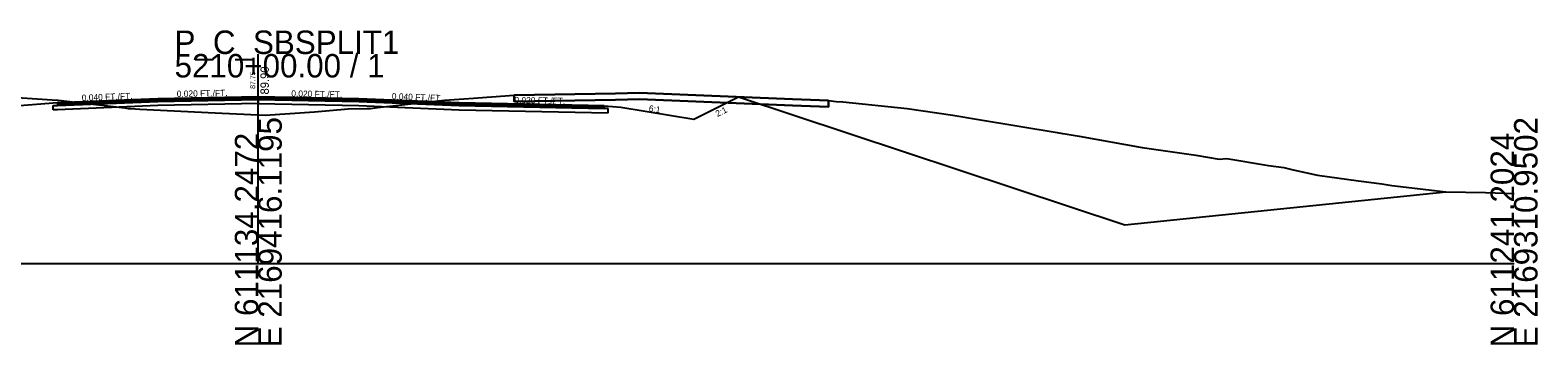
# Model space of a CAD drawing. Extents: x -26 to 1303, y -3010 to 12033.
# Drawn here: x 1122.8 to 1302.8, y 6990.3 to 7027.8 of the extents above; entities that cross this region are included whole.
import ezdxf

# ---------------------------------------------------------------- set-up
doc = ezdxf.new("R2010")
doc.units = 0
for name, color, linetype in [('RD_GPK_XS_Cell', 7, 'Continuous'), ('RD_Sketch10', 7, 'Continuous'), ('RD_XS_Base', 7, 'Continuous'), ('RD_XS_ExGround', 7, 'Continuous'), ('RD_XS_ExPaveRet', 7, 'Continuous'), ('RD_XS_Greenside', 7, 'Continuous'), ('RD_XS_Pave', 7, 'Continuous'), ('RD_XS_PaveOvlay_CP', 7, 'Continuous'), ('RD_XS_TieSlope', 7, 'Continuous'), ('RD_XS_TX_Elev_EX', 7, 'Continuous'), ('RD_XS_TX_Elev_PR', 7, 'Continuous'), ('RD_XS_TX_Slope', 7, 'Continuous')]:
    doc.layers.add(name, color=color, linetype=linetype)

msp = doc.modelspace()

# ---------------------------------------------------------------- linework, layer by layer
at = {"layer": 'RD_GPK_XS_Cell'}
for p, q in [((1150, 7000), (1150, 7025)), ((1000, 7000), (1150, 7000)), ((1150, 7000), (1300, 7000))]:
    msp.add_line(p, q, dxfattribs=at)
at = {"layer": 'RD_Sketch10'}
msp.add_lwpolyline([(1207.36, 7019.88), (1253.51, 7004.61), (1291.86, 7008.57)], dxfattribs=at)
at = {"layer": 'RD_XS_Base'}
for p, q in [((1125.5, 7018.84), (1126, 7018.86)), ((1125.5, 7018.34), (1125.5, 7018.84)), ((1125.5, 7018.84), (1125.5, 7018.84)), ((1126, 7018.36), (1125.5, 7018.34)), ((1125.5, 7018.34), (1125.5, 7018.34)), ((1125.5, 7018.34), (1125.5, 7018.34)), ((1126, 7018.86), (1138, 7019.34)), ((1126, 7018.86), (1126, 7018.86)), ((1138, 7018.84), (1126, 7018.36)), ((1126, 7018.36), (1126, 7018.36)), ((1136, 7019.26), (1136, 7019.26)), ((1136, 7018.76), (1136, 7018.76)), ((1138, 7019.34), (1150, 7019.58)), ((1150, 7019.08), (1138, 7018.84)), ((1150, 7019.58), (1150, 7019.74)), ((1150, 7019.74), (1150, 7019.08)), ((1150, 7019.58), (1150, 7019.08)), ((1150, 7019.58), (1150, 7019.58)), ((1162, 7019.34), (1150, 7019.58)), ((1150, 7019.58), (1150, 7019.58)), ((1150, 7019.08), (1150, 7019.08)), ((1150, 7019.08), (1150, 7019.08)), ((1150, 7019.08), (1162, 7018.84)), ((1174, 7018.86), (1162, 7019.34)), ((1162, 7019.34), (1162, 7019.34)), ((1162, 7018.84), (1162, 7018.84)), ((1162, 7018.84), (1174, 7018.36)), ((1191.3, 7018.51), (1174, 7018.86)), ((1174, 7018.86), (1174, 7018.86)), ((1174, 7018.36), (1174, 7018.36)), ((1174, 7018.36), (1191.8, 7018)), ((1191.8, 7018.5), (1191.3, 7018.51)), ((1191.3, 7018.51), (1191.3, 7018.51)), ((1191.8, 7018), (1191.8, 7018.5)), ((1191.8, 7018.5), (1191.8, 7018.5)), ((1191.8, 7018), (1191.8, 7018)), ((1191.8, 7018), (1191.8, 7018))]:
    msp.add_line(p, q, dxfattribs=at)
at = {"layer": 'RD_XS_ExGround'}
msp.add_lwpolyline([(1116.42, 7020.14), (1125.36, 7019.55), (1126.03, 7019.51), (1126.08, 7019.51), (1134.06, 7018.56), (1134.47, 7018.5), (1134.56, 7018.5), (1134.72, 7018.49), (1135.86, 7018.43), (1144.86, 7017.97), (1150.84, 7017.71), (1156.71, 7018.12), (1160.72, 7018.44), (1162.99, 7018.49), (1163.39, 7018.51), (1164.24, 7018.6), (1172.26, 7019.5), (1175.15, 7019.69), (1180.58, 7020.08), (1192.67, 7020.3), (1195.54, 7020.36), (1213.82, 7019.62), (1218.12, 7019.45), (1219.03, 7019.35), (1219.82, 7019.28), (1227.5, 7018.5), (1232.97, 7017.69), (1236.04, 7017.2), (1245.43, 7015.63), (1246.05, 7015.5), (1246.36, 7015.49), (1248.04, 7015.19), (1255.58, 7013.86), (1261.98, 7012.94), (1264.77, 7012.47), (1265.69, 7012.55), (1270.65, 7011.69), (1272.51, 7011.45), (1273.63, 7011.2), (1276.52, 7010.54), (1281.42, 7009.87), (1284.21, 7009.5), (1285.38, 7009.31), (1291.86, 7008.57), (1296.6, 7008.47), (1300, 7008.36)], dxfattribs=at)
at = {"layer": 'RD_XS_ExPaveRet'}
for points in [[(1218.12, 7019.45), (1218.12, 7018.7), (1218.12, 7018.7), (1218.12, 7018.7), (1218.12, 7018.7), (1213.82, 7018.87), (1213.82, 7018.87), (1195.54, 7019.61), (1195.54, 7019.61), (1192.67, 7019.55), (1192.67, 7019.55), (1180.58, 7019.33), (1180.58, 7020.08), (1180.58, 7020.08), (1192.67, 7020.3), (1192.67, 7020.3), (1195.54, 7020.36), (1195.54, 7020.36), (1213.82, 7019.62), (1213.82, 7019.62), (1218.12, 7019.45), (1218.12, 7019.45), (1218.12, 7019.45)], [(1218.12, 7019.45), (1213.82, 7019.62), (1195.54, 7020.36), (1192.67, 7020.3), (1180.58, 7020.08), (1180.58, 7019.33), (1192.67, 7019.55), (1195.54, 7019.61), (1213.82, 7018.87), (1218.12, 7018.7), (1218.12, 7018.7), (1218.12, 7019.45), (1218.12, 7019.45)]]:
    msp.add_lwpolyline(points, dxfattribs=at)
at = {"layer": 'RD_XS_Greenside'}
for p, q in [((1193.3, 7018.67), (1202.03, 7017.22)), ((1202.03, 7017.22), (1207.36, 7019.88))]:
    msp.add_line(p, q, dxfattribs=at)
at = {"layer": 'RD_XS_Pave'}
for p, q in [((1138, 7019.66), (1126, 7019.18)), ((1138, 7019.5), (1126, 7019.02)), ((1126, 7019.02), (1138, 7019.5)), ((1126, 7018.86), (1138, 7019.34)), ((1126, 7019.18), (1126, 7019.18)), ((1126, 7019.18), (1126, 7019.02)), ((1126, 7019.02), (1126, 7019.02)), ((1126, 7019.02), (1126, 7018.86)), ((1126, 7019.02), (1126, 7019.02)), ((1126, 7019.02), (1126, 7019.02)), ((1126, 7018.86), (1126, 7018.86)), ((1126, 7018.86), (1126, 7018.86)), ((1136, 7019.58), (1136, 7019.58)), ((1136, 7019.42), (1136, 7019.42)), ((1136, 7019.42), (1136, 7019.42)), ((1136, 7019.26), (1136, 7019.26)), ((1150, 7019.9), (1138, 7019.66)), ((1150, 7019.74), (1138, 7019.5)), ((1138, 7019.5), (1150, 7019.74)), ((1138, 7019.34), (1150, 7019.58)), ((1162, 7019.66), (1150, 7019.9)), ((1150, 7019.58), (1150, 7019.74)), ((1150, 7019.74), (1162, 7019.5)), ((1162, 7019.5), (1150, 7019.74)), ((1150, 7019.74), (1150, 7019.74)), ((1150, 7019.74), (1150, 7019.58)), ((1150, 7019.58), (1150, 7019.58)), ((1150, 7019.58), (1150, 7019.58)), ((1150, 7019.58), (1150, 7019.58)), ((1150, 7019.58), (1162, 7019.34)), ((1174, 7019.18), (1162, 7019.66)), ((1162, 7019.66), (1162, 7019.66)), ((1162, 7019.5), (1162, 7019.5)), ((1162, 7019.5), (1174, 7019.02)), ((1174, 7019.02), (1162, 7019.5)), ((1162, 7019.5), (1162, 7019.5)), ((1162, 7019.34), (1162, 7019.34)), ((1162, 7019.34), (1174, 7018.86)), ((1191.3, 7018.83), (1174, 7019.18)), ((1174, 7019.18), (1174, 7019.18)), ((1174, 7019.02), (1174, 7019.02)), ((1174, 7019.02), (1191.3, 7018.67)), ((1191.3, 7018.67), (1174, 7019.02)), ((1174, 7019.02), (1174, 7019.02)), ((1174, 7018.86), (1174, 7018.86)), ((1174, 7018.86), (1191.3, 7018.51)), ((1191.3, 7018.67), (1191.3, 7018.83)), ((1191.3, 7018.83), (1191.3, 7018.83)), ((1191.3, 7018.67), (1191.3, 7018.67)), ((1191.3, 7018.67), (1191.3, 7018.67)), ((1191.3, 7018.51), (1191.3, 7018.67)), ((1191.3, 7018.67), (1191.3, 7018.67)), ((1191.3, 7018.51), (1191.3, 7018.51)), ((1191.3, 7018.51), (1191.3, 7018.51))]:
    msp.add_line(p, q, dxfattribs=at)
at = {"layer": 'RD_XS_PaveOvlay_CP'}
for p, q in [((1138, 7019.66), (1126, 7019.18)), ((1126, 7019.18), (1126, 7019.18)), ((1136, 7019.58), (1136, 7019.58)), ((1150, 7019.9), (1138, 7019.66)), ((1162, 7019.66), (1150, 7019.9)), ((1174, 7019.18), (1162, 7019.66)), ((1162, 7019.66), (1162, 7019.66)), ((1191.3, 7018.83), (1174, 7019.18)), ((1174, 7019.18), (1174, 7019.18)), ((1191.3, 7018.83), (1191.3, 7018.83))]:
    msp.add_line(p, q, dxfattribs=at)
at = {"layer": 'RD_XS_TieSlope'}
for p, q in [((1126, 7019.18), (1120, 7018.7)), ((1191.3, 7018.83), (1193.3, 7018.67))]:
    msp.add_line(p, q, dxfattribs=at)

# ---------------------------------------------------------------- texts
at = {"layer": 'RD_GPK_XS_Cell'}
for s, p in [('P_C_SBSPLIT1', (1140, 7025)), ('5210+00.00 / 1', (1140, 7022.2))]:
    msp.add_text(s, height=2.8, dxfattribs=at).set_placement(p)
for s, p in [('E 2169416.1195', (1152.8, 6990)), ('E 2169310.9502', (1302.8, 6990)), ('N 611134.2472', (1150, 6990)), ('N 611241.2024', (1300, 6990))]:
    msp.add_text(s, height=2.8, rotation=90, dxfattribs=at).set_placement(p)
at = {"layer": 'RD_XS_TX_Elev_EX'}
msp.add_text('87.75', height=0.6, rotation=90, dxfattribs=at).set_placement((1149.63, 7020.84))
at = {"layer": 'RD_XS_TX_Elev_PR'}
msp.add_text('89.90', height=1, rotation=90, dxfattribs=at).set_placement((1151.26, 7020.17))
at = {"layer": 'RD_XS_TX_Slope'}
for s, rotation, p in [('0.040 FT./FT.', 2.2906, (1128.93, 7019.39)), ('0.020 FT./FT.', 1.1458, (1140.27, 7019.87)), ('0.020 FT./FT.', 358.8542, (1153.94, 7019.92)), ('0.040 FT./FT.', 357.7094, (1165.94, 7019.6)), ('0.020 FT./FT.', 358.8542, (1180.59, 7019.14)), ('6:1', 350.5377, (1196.6, 7018.18)), ('2:1', 26.5651, (1204.84, 7017.47))]:
    msp.add_text(s, height=0.75, rotation=rotation, dxfattribs=at).set_placement(p)

doc.saveas('drawing.dxf')
